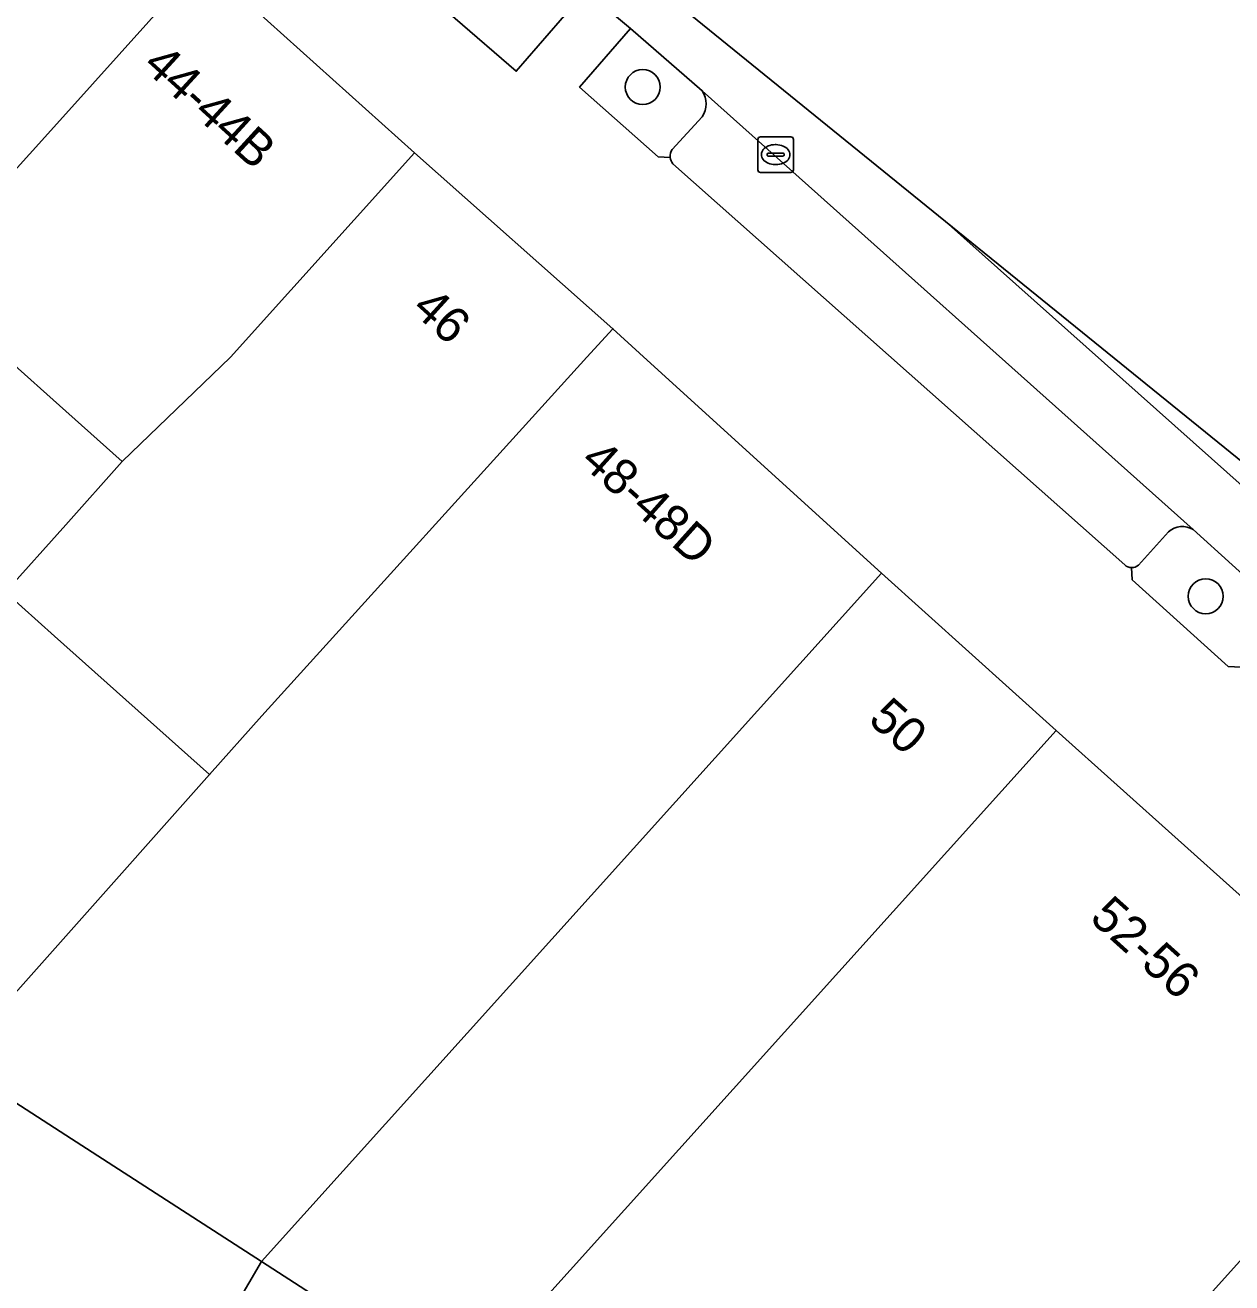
# Model space of a CAD drawing. Extents: x 161798 to 162385, y 382315 to 382833.
# Drawn here: x 161998.86 to 162032.68, y 382724.06 to 382759.31 of the extents above; entities that cross this region are included whole.
import ezdxf

# ---------------------------------------------------------------- set-up
doc = ezdxf.new("R2010")
doc.units = 0
for name, color, linetype in [('IMGEO_Boom', 7, 'Continuous'), ('IMGEO_Erf', 7, 'Continuous'), ('IMGEO_Groenvoorziening', 7, 'Continuous'), ('IMGEO_Kolk', 7, 'Continuous'), ('IMGEO_Pand', 7, 'Continuous'), ('IMGEO_Pand_nummerreeks', 7, 'Continuous'), ('IMGEO_Parkeervlak_open', 7, 'Continuous'), ('IMGEO_Rijbaan_lokaal_gesloten', 7, 'Continuous'), ('IMGEO_Rijbaan_lokaal_open', 7, 'Continuous'), ('IMGEO_Voetpad_open', 7, 'Continuous')]:
    doc.layers.add(name, color=color, linetype=linetype)

msp = doc.modelspace()

# ---------------------------------------------------------------- linework, layer by layer
at = {"layer": 'IMGEO_Boom'}
for centre in [(162016.17, 382757.573), (162031.945, 382743.3)]:
    msp.add_circle(centre, 0.489, dxfattribs=at)
at = {"layer": 'IMGEO_Erf'}
msp.add_lwpolyline([(161996.854, 382709.902), (162005.49, 382724.651), (162000, 382728.195), (161996.847, 382730.23), (162000, 382733.772), (162004.032, 382738.302), (161999.682, 382742.186), (161998.309, 382743.412), (162000, 382745.307), (162001.581, 382747.078), (162000, 382748.49), (161998.309, 382750)], dxfattribs=at)
at = {"layer": 'IMGEO_Groenvoorziening'}
for points in [[(162005.677, 382766.977), (162005.224, 382767.376), (162003.748, 382765.691), (162007.491, 382762.457), (162012.625, 382758.014), (162014.168, 382759.79)], [(162017.838, 382757.467), (162015.823, 382759.219), (162014.402, 382757.569), (162016.605, 382755.616), (162016.94, 382755.601)], [(162016.999, 382755.824), (162017.835, 382756.741)], [(162030.903, 382745.106), (162030.063, 382744.17)], [(162033.82, 382743.154), (162033.775, 382743.194), (162031.597, 382745.168)], [(162029.87, 382744.103), (162029.886, 382743.76), (162032.575, 382741.336), (162032.926, 382741.313)]]:
    msp.add_lwpolyline(points, dxfattribs=at)
for centre, radius, start, end in [((162017.294, 382757.106), 0.653, 325.9638, 33.5627), ((162017.262, 382755.635), 0.324, 144.3261, 186.035), ((162031.291, 382744.679), 0.577, 57.9514, 132.2588), ((162029.876, 382744.397), 0.294, 268.7914, 309.4975)]:
    msp.add_arc(centre, radius, start, end, dxfattribs=at)
at = {"layer": 'IMGEO_Kolk'}
for p, q in [((162019.394, 382755.253), (162019.394, 382756.105)), ((162019.469, 382756.179), (162020.321, 382756.179)), ((162020.395, 382756.105), (162020.395, 382755.253)), ((162019.882, 382755.959), (162019.907, 382755.959)), ((162019.653, 382755.673), (162019.653, 382755.685)), ((162020.091, 382755.636), (162019.693, 382755.636)), ((162019.696, 382755.722), (162020.094, 382755.722)), ((162020.137, 382755.685), (162020.137, 382755.673)), ((162020.321, 382755.179), (162019.469, 382755.179)), ((162019.905, 382755.399), (162019.88, 382755.399))]:
    msp.add_line(p, q, dxfattribs=at)
for points in [[(162019.394, 382755.253), (162019.394, 382756.105)], [(162019.469, 382756.179), (162020.321, 382756.179)], [(162020.395, 382756.105), (162020.395, 382755.253)], [(162020.321, 382755.179), (162019.469, 382755.179)]]:
    msp.add_lwpolyline(points, dxfattribs=at)
for centre, radius, start, end in [((162019.471, 382756.103), 0.0765, 91.552, 178.448), ((162019.471, 382756.103), 0.0765, 91.552, 178.448), ((162020.319, 382756.103), 0.0765, 1.552, 88.448), ((162020.319, 382756.103), 0.0765, 1.552, 88.448), ((162019.693, 382755.682), 0.0403, 85.8775, 175.7526), ((162019.69, 382755.672), 0.0366, 178.938, 274.7102), ((162020.094, 382755.679), 0.043, 264.8664, 352.4533), ((162020.098, 382755.684), 0.0386, 1.7309, 96.639), ((162019.471, 382755.255), 0.0765, 181.552, 268.448), ((162019.471, 382755.255), 0.0765, 181.552, 268.448), ((162020.319, 382755.255), 0.0765, 271.552, 358.448), ((162020.319, 382755.255), 0.0765, 271.552, 358.448)]:
    msp.add_arc(centre, radius, start, end, dxfattribs=at)
for centre, major_axis, ratio, start_param, end_param in [((162019.881, 382755.679), (-0.387, 0.002), 0.722429, 4.712389, 7.853982), ((162019.906, 382755.679), (-0.39, 0.002), 0.717154, 1.570796, 4.712389)]:
    msp.add_ellipse(centre, major_axis=major_axis, ratio=ratio, start_param=start_param, end_param=end_param, dxfattribs=at)
at = {"layer": 'IMGEO_Pand'}
for points in [[(162000, 382756.824), (162003.821, 382761.079), (162000, 382764.491), (161998.609, 382765.767), (161997.519, 382764.558), (161984.249, 382750), (161981.747, 382747.198), (161985.478, 382743.87), (161987.064, 382742.454), (161991.557, 382747.445), (161991.488, 382747.507), (161993.712, 382750), (161995.75, 382752.284), (161995.84, 382752.203)], [(162009.776, 382755.729), (162003.821, 382761.079), (162000, 382756.824), (161995.84, 382752.203), (161998.309, 382750), (162000, 382748.49), (162001.581, 382747.078), (162004.62, 382750)], [(162014.601, 382750), (162015.335, 382750.798), (162009.776, 382755.729), (162004.62, 382750), (162001.581, 382747.078), (162000, 382745.307), (161998.309, 382743.412), (161999.682, 382742.186), (162004.032, 382738.302), (162005.499, 382739.95)], [(162022.858, 382743.945), (162017.324, 382748.986), (162016.083, 382750.117), (162015.335, 382750.798), (162014.601, 382750), (162005.499, 382739.95), (162004.032, 382738.302), (162000, 382733.772), (161996.847, 382730.23), (162000, 382728.195), (162005.49, 382724.651)], [(162027.754, 382739.543), (162022.858, 382743.945), (162005.49, 382724.651), (162011.093, 382721.034)], [(162038.012, 382730.344), (162027.754, 382739.543), (162011.093, 382721.034), (162011.249, 382720.933), (162020.899, 382711.331), (162027.277, 382718.416), (162031.391, 382722.985)], [(162043.809, 382725.145), (162038.012, 382730.344), (162031.391, 382722.985), (162034.809, 382719.922), (162031.855, 382714.755), (162030.255, 382715.747), (162027.277, 382718.416), (162020.899, 382711.331), (162021.086, 382711.145), (162027.742, 382707.225), (162032.096, 382704.768), (162039.623, 382717.887), (162038.323, 382719.109)]]:
    msp.add_lwpolyline(points, close=True, dxfattribs=at)
at = {"layer": 'IMGEO_Parkeervlak_open'}
for points in [[(162031.597, 382745.168), (162017.838, 382757.467)], [(162017.835, 382756.741), (162016.999, 382755.824)], [(162017.017, 382755.424), (162029.678, 382744.178)], [(162030.063, 382744.17), (162030.903, 382745.106)]]:
    msp.add_lwpolyline(points, dxfattribs=at)
for centre, radius, start, end in [((162017.294, 382757.106), 0.653, 325.9638, 33.5627), ((162017.262, 382755.635), 0.324, 144.3261, 186.035), ((162017.265, 382755.637), 0.327, 186.3365, 220.6843), ((162031.291, 382744.679), 0.577, 57.9514, 132.2588), ((162029.873, 382744.394), 0.291, 227.9367, 269.3896), ((162029.876, 382744.397), 0.294, 268.7914, 309.4975)]:
    msp.add_arc(centre, radius, start, end, dxfattribs=at)
at = {"layer": 'IMGEO_Rijbaan_lokaal_gesloten'}
msp.add_lwpolyline([(162024.654, 382753.809), (161999.533, 382774.178), (161998.874, 382773.374), (162015.823, 382759.219), (162017.838, 382757.467), (162031.597, 382745.168), (162033.775, 382743.194), (162033.82, 382743.154), (162036.171, 382741.054), (162043.452, 382734.52), (162045.887, 382732.315), (162046.684, 382731.604), (162048.13, 382730.285), (162049.418, 382731.719), (162037.507, 382742.354)], close=True, dxfattribs=at)
at = {"layer": 'IMGEO_Rijbaan_lokaal_open'}
msp.add_lwpolyline([(162050.126, 382732.448), (162041.198, 382740.395), (162024.654, 382753.809), (162037.507, 382742.354), (162049.418, 382731.719)], close=True, dxfattribs=at)
msp.add_lwpolyline([(161992.884, 382681.874), (161999.451, 382694.354), (162002.565, 382700.272), (162006.112, 382707.087), (162005.878, 382707.219), (162005.59, 382707.381), (162009.229, 382713.086), (162014.021, 382710.386), (162023.554, 382705.016), (162025.696, 382703.81), (162030.046, 382701.359), (162032.096, 382704.768), (162027.742, 382707.225), (162021.086, 382711.145), (162020.899, 382711.331), (162011.249, 382720.933), (162011.093, 382721.034), (162005.49, 382724.651), (161996.854, 382709.902)], dxfattribs=at)
at = {"layer": 'IMGEO_Voetpad_open'}
for points in [[(162016.94, 382755.601), (162016.605, 382755.616), (162014.402, 382757.569), (162015.823, 382759.219), (161998.874, 382773.374)], [(161994.37, 382772.717), (161991.783, 382769.02), (161991.848, 382768.97), (161997.519, 382764.558), (161998.609, 382765.767), (162000, 382764.491), (162003.821, 382761.079), (162009.776, 382755.729), (162015.335, 382750.798), (162016.083, 382750.117), (162017.324, 382748.986), (162022.858, 382743.945), (162027.754, 382739.543), (162038.012, 382730.344), (162043.809, 382725.145), (162045.819, 382722.219)], [(162012.625, 382758.014), (162007.491, 382762.457), (162003.748, 382765.691), (162005.224, 382767.376), (162005.677, 382766.977)], [(162012.313, 382761.387), (162014.168, 382759.79), (162012.625, 382758.014)], [(162029.678, 382744.178), (162017.017, 382755.424)], [(162032.926, 382741.313), (162032.575, 382741.336), (162029.886, 382743.76), (162029.87, 382744.103)]]:
    msp.add_lwpolyline(points, dxfattribs=at)
for centre, radius, start, end in [((162017.265, 382755.637), 0.327, 186.3365, 220.6843), ((162029.873, 382744.394), 0.291, 227.9367, 269.3896)]:
    msp.add_arc(centre, radius, start, end, dxfattribs=at)

# ---------------------------------------------------------------- texts
at = {"layer": 'IMGEO_Pand_nummerreeks'}
for s, rotation, p in [('44-44B', 317.5782, (162002.121, 382758.125)), ('46', 317.8017, (162009.66, 382751.304)), ('48-48D', 318.0939, (162014.383, 382747.035)), ('50', 318.1282, (162022.453, 382739.795)), ('52-56', 318.1282, (162028.657, 382734.234))]:
    msp.add_text(s, height=1, rotation=rotation, dxfattribs=at).set_placement(p)

doc.saveas('drawing.dxf')
